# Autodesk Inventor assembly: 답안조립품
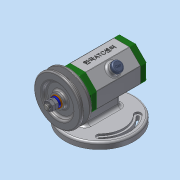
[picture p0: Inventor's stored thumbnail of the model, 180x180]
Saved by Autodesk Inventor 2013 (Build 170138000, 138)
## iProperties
Created: 2017-06
Part Number: 답안조립품
Document SubType Name: Assembly
Designer: narae
Author: narae
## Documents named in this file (14)
- C:\Users\narae\Desktop\470608V1006\답안조립품.iam
- C:\Users\narae\Desktop\470608V1006\본체.ipt
- C:\Users\narae\Desktop\470608V1006\축.ipt
- C:\Users\narae\Desktop\470608V1006\키 3 x 3 x 12.ipt
- C:\Users\narae\Desktop\470608V1006\베어링 15 x 32 x 9.ipt
- C:\Users\narae\Desktop\470608V1006\앞커버.ipt
- C:\Users\narae\Desktop\470608V1006\뒤커버.ipt
- C:\Users\narae\Desktop\470608V1006\오일 실 15 25 7.ipt
- C:\Users\narae\Desktop\470608V1006\볼트 M4 x 12.ipt
- C:\Users\narae\Desktop\470608V1006\V벨트풀리.ipt
- C:\Users\narae\Desktop\470608V1006\와셔 8x17.ipt
- C:\Users\narae\Desktop\470608V1006\스프링와셔 8.ipt
- C:\Users\narae\Desktop\470608V1006\너트 M 8.ipt
- C:\Users\narae\Desktop\470608V1006\고무캡.ipt
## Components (2 placed, 2 different names)
1. V벨트풀리:1
2. 고무캡:1
